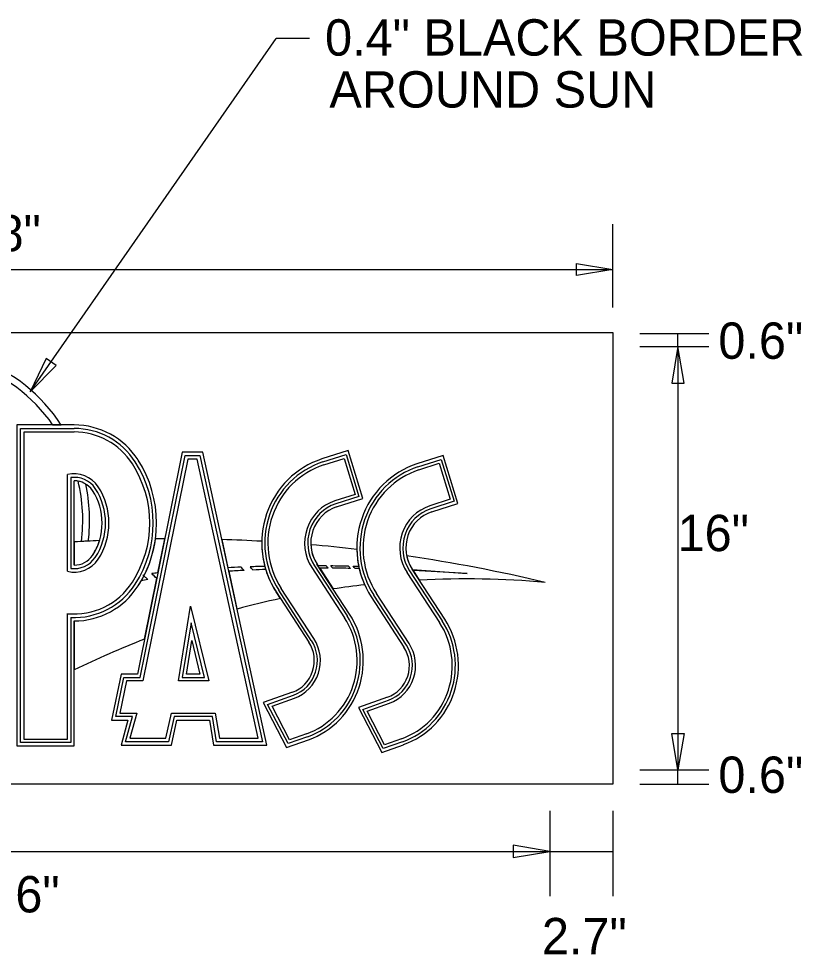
# Model space of a CAD drawing. Extents: x 10268197 to 10268738, y 2141503 to 2142677.
# Drawn here: x 10268688.05 to 10268703.13, y 2142372.22 to 2142390.23 of the extents above; entities that cross this region are included whole.
import ezdxf

# ---------------------------------------------------------------- set-up
doc = ezdxf.new("R2010")
doc.units = 0
for name, color, linetype in [('1', 7, 'Continuous'), ('Default', 7, 'Continuous'), ('GSDims', 7, 'Continuous'), ('TextMisc', 7, 'Continuous')]:
    doc.layers.add(name, color=color, linetype=linetype)

msp = doc.modelspace()

# ---------------------------------------------------------------- linework, layer by layer
at = {"layer": '1'}
for p, q in [((10268688.273, 2142383.048), (10268693.006, 2142389.854)), ((10268693.645, 2142389.854), (10268693.006, 2142389.854)), ((10268690.389, 2142377.551), (10268691.254, 2142381.823)), ((10268691.254, 2142381.823), (10268691.538, 2142381.823)), ((10268691.538, 2142381.823), (10268692.74, 2142376.315)), ((10268690.61, 2142379.551), (10268690.701, 2142379.461)), ((10268691.369, 2142378.6), (10268691.198, 2142377.551)), ((10268691.625, 2142377.551), (10268691.369, 2142378.6)), ((10268689.918, 2142376.798), (10268690.074, 2142377.551)), ((10268690.074, 2142377.551), (10268690.389, 2142377.551)), ((10268691.198, 2142377.551), (10268691.625, 2142377.551)), ((10268691.539, 2142377.618), (10268691.277, 2142377.618)), ((10268690.238, 2142376.798), (10268689.918, 2142376.798)), ((10268690.107, 2142376.315), (10268690.238, 2142376.798)), ((10268691.04, 2142376.798), (10268690.935, 2142376.315)), ((10268691.78, 2142376.798), (10268691.04, 2142376.798)), ((10268691.859, 2142376.315), (10268691.78, 2142376.798)), ((10268689.836, 2142376.731), (10268690.15, 2142376.731)), ((10268690.935, 2142376.315), (10268690.107, 2142376.315)), ((10268692.74, 2142376.315), (10268691.859, 2142376.315)), ((10268699.488, 2142375.495), (10268675.901, 2142375.495))]:
    msp.add_line(p, q, dxfattribs=at)
for points in [[(10268690.15, 2142376.731), (10268690.019, 2142376.248), (10268690.989, 2142376.248), (10268691.094, 2142376.731), (10268691.723, 2142376.731), (10268691.802, 2142376.248), (10268692.824, 2142376.248), (10268691.592, 2142381.89), (10268691.199, 2142381.89), (10268690.334, 2142377.618), (10268690.019, 2142377.618), (10268689.836, 2142376.731)], [(10268690.442, 2142379.529), (10268690.538, 2142379.435), (10268690.409, 2142379.413)], [(10268691.277, 2142377.618), (10268691.382, 2142378.263), (10268691.539, 2142377.618)]]:
    msp.add_lwpolyline(points, dxfattribs=at)
at = {"layer": 'Default'}
for p, q in [((10268688.709, 2142382.412), (10268688.869, 2142382.412)), ((10268688.083, 2142376.299), (10268688.083, 2142382.345)), ((10268688.083, 2142382.345), (10268689.118, 2142382.345)), ((10268688.148, 2142382.277), (10268688.148, 2142376.366)), ((10268689.118, 2142382.277), (10268688.148, 2142382.277)), ((10268688.148, 2142382.277), (10268688.148, 2142376.366)), ((10268689.118, 2142382.277), (10268688.148, 2142382.277)), ((10268693.902, 2142381.7), (10268694.351, 2142381.845)), ((10268694.351, 2142381.845), (10268694.599, 2142381.038)), ((10268691.305, 2142381.756), (10268690.44, 2142377.484)), ((10268691.305, 2142381.756), (10268690.44, 2142377.484)), ((10268691.487, 2142381.756), (10268691.305, 2142381.756)), ((10268691.487, 2142381.756), (10268691.305, 2142381.756)), ((10268692.66, 2142376.382), (10268691.487, 2142381.756)), ((10268692.66, 2142376.382), (10268691.487, 2142381.756)), ((10268693.92, 2142381.642), (10268694.312, 2142381.769)), ((10268693.92, 2142381.642), (10268694.312, 2142381.769)), ((10268694.312, 2142381.769), (10268694.525, 2142381.077)), ((10268694.312, 2142381.769), (10268694.525, 2142381.077)), ((10268695.733, 2142381.605), (10268696.181, 2142381.75)), ((10268695.751, 2142381.547), (10268696.143, 2142381.674)), ((10268695.751, 2142381.547), (10268696.143, 2142381.674)), ((10268696.143, 2142381.674), (10268696.356, 2142380.982)), ((10268696.143, 2142381.674), (10268696.356, 2142380.982)), ((10268696.181, 2142381.75), (10268696.43, 2142380.943)), ((10268688.987, 2142379.595), (10268688.987, 2142381.456)), ((10268688.987, 2142379.595), (10268688.987, 2142381.456)), ((10268689.053, 2142381.399), (10268689.053, 2142379.651)), ((10268689.118, 2142379.714), (10268689.118, 2142381.337)), ((10268694.525, 2142381.077), (10268694.133, 2142380.951)), ((10268694.525, 2142381.077), (10268694.133, 2142380.951)), ((10268694.599, 2142381.038), (10268694.151, 2142380.893)), ((10268696.356, 2142380.982), (10268695.964, 2142380.855)), ((10268696.356, 2142380.982), (10268695.964, 2142380.855)), ((10268696.43, 2142380.943), (10268695.982, 2142380.797)), ((10268690.728, 2142379.565), (10268690.861, 2142380.22)), ((10268689.118, 2142380.161), (10268689.118, 2142379.714)), ((10268691.959, 2142380.207), (10268692.078, 2142379.664)), ((10268689.469, 2142379.899), (10268689.469, 2142379.899)), ((10268693.742, 2142379.701), (10268694.369, 2142378.736)), ((10268694.418, 2142378.769), (10268693.791, 2142379.734)), ((10268693.791, 2142379.734), (10268693.812, 2142379.701)), ((10268692.093, 2142379.596), (10268692.251, 2142378.87)), ((10268693.693, 2142379.667), (10268694.32, 2142378.702)), ((10268693.693, 2142379.667), (10268694.32, 2142378.702)), ((10268693.843, 2142379.653), (10268694.102, 2142379.256)), ((10268695.523, 2142379.572), (10268696.151, 2142378.607)), ((10268695.523, 2142379.572), (10268696.151, 2142378.607)), ((10268695.572, 2142379.605), (10268696.2, 2142378.64)), ((10268696.249, 2142378.674), (10268695.621, 2142379.639)), ((10268695.621, 2142379.639), (10268695.627, 2142379.63)), ((10268695.627, 2142379.63), (10268696.682, 2142379.553)), ((10268696.682, 2142379.553), (10268695.641, 2142379.608)), ((10268695.641, 2142379.608), (10268695.76, 2142379.425)), ((10268690.348, 2142379.313), (10268690.348, 2142379.313)), ((10268690.469, 2142378.288), (10268690.707, 2142379.46)), ((10268693.006, 2142379.198), (10268693.633, 2142378.232)), ((10268693.088, 2142379.071), (10268693.006, 2142379.198)), ((10268693.682, 2142378.266), (10268693.055, 2142379.231)), ((10268693.731, 2142378.3), (10268693.104, 2142379.265)), ((10268693.731, 2142378.3), (10268693.104, 2142379.265)), ((10268695.513, 2142378.171), (10268694.885, 2142379.136)), ((10268695.562, 2142378.204), (10268694.934, 2142379.169)), ((10268695.562, 2142378.204), (10268694.934, 2142379.169)), ((10268694.836, 2142379.102), (10268695.464, 2142378.137)), ((10268688.987, 2142376.366), (10268688.987, 2142378.78)), ((10268688.987, 2142376.366), (10268688.987, 2142378.78)), ((10268691.123, 2142377.484), (10268691.356, 2142378.922)), ((10268691.123, 2142377.484), (10268691.356, 2142378.922)), ((10268691.356, 2142378.922), (10268691.707, 2142377.484)), ((10268691.356, 2142378.922), (10268691.707, 2142377.484)), ((10268689.053, 2142378.708), (10268689.053, 2142376.299)), ((10268689.118, 2142378.639), (10268689.118, 2142377.696)), ((10268690.125, 2142377.484), (10268689.997, 2142376.866)), ((10268690.125, 2142377.484), (10268689.997, 2142376.866)), ((10268690.44, 2142377.484), (10268690.125, 2142377.484)), ((10268690.44, 2142377.484), (10268690.125, 2142377.484)), ((10268691.707, 2142377.484), (10268691.123, 2142377.484)), ((10268691.707, 2142377.484), (10268691.123, 2142377.484)), ((10268692.841, 2142377.033), (10268693.336, 2142377.209)), ((10268692.925, 2142376.999), (10268693.355, 2142377.152)), ((10268692.925, 2142376.999), (10268693.355, 2142377.152)), ((10268693.234, 2142376.277), (10268692.841, 2142377.033)), ((10268693.262, 2142376.351), (10268692.925, 2142376.999)), ((10268693.262, 2142376.351), (10268692.925, 2142376.999)), ((10268694.672, 2142376.937), (10268695.167, 2142377.114)), ((10268694.756, 2142376.903), (10268695.186, 2142377.057)), ((10268694.756, 2142376.903), (10268695.186, 2142377.057)), ((10268689.997, 2142376.866), (10268690.323, 2142376.866)), ((10268689.997, 2142376.866), (10268690.323, 2142376.866)), ((10268690.323, 2142376.866), (10268690.192, 2142376.382)), ((10268690.323, 2142376.866), (10268690.192, 2142376.382)), ((10268690.884, 2142376.382), (10268690.989, 2142376.866)), ((10268690.884, 2142376.382), (10268690.989, 2142376.866)), ((10268690.989, 2142376.866), (10268691.834, 2142376.866)), ((10268690.989, 2142376.866), (10268691.834, 2142376.866)), ((10268691.834, 2142376.866), (10268691.913, 2142376.382)), ((10268691.834, 2142376.866), (10268691.913, 2142376.382)), ((10268695.065, 2142376.181), (10268694.672, 2142376.937)), ((10268695.093, 2142376.255), (10268694.756, 2142376.903)), ((10268695.093, 2142376.255), (10268694.756, 2142376.903)), ((10268693.588, 2142376.467), (10268693.262, 2142376.351)), ((10268693.588, 2142376.467), (10268693.262, 2142376.351)), ((10268689.053, 2142376.299), (10268688.083, 2142376.299)), ((10268688.148, 2142376.366), (10268688.987, 2142376.366)), ((10268688.148, 2142376.366), (10268688.987, 2142376.366)), ((10268690.192, 2142376.382), (10268690.884, 2142376.382)), ((10268690.192, 2142376.382), (10268690.884, 2142376.382)), ((10268691.913, 2142376.382), (10268692.66, 2142376.382)), ((10268691.913, 2142376.382), (10268692.66, 2142376.382)), ((10268693.607, 2142376.41), (10268693.234, 2142376.277)), ((10268695.438, 2142376.314), (10268695.065, 2142376.181)), ((10268695.419, 2142376.371), (10268695.093, 2142376.255)), ((10268695.419, 2142376.371), (10268695.093, 2142376.255)), ((10268699.488, 2142375.495), (10268675.901, 2142375.495))]:
    msp.add_line(p, q, dxfattribs=at)
for points in [[(10268675.901, 2142375.495), (10268675.901, 2142384.193), (10268699.488, 2142384.193), (10268699.488, 2142375.495)], [(10268689.118, 2142382.412), (10268688.017, 2142382.412), (10268688.017, 2142376.232), (10268689.118, 2142376.232), (10268689.118, 2142378.639)], [(10268694.169, 2142380.835), (10268694.673, 2142380.999), (10268694.389, 2142381.921), (10268693.885, 2142381.758)], [(10268690.293, 2142381.701), (10268690.293, 2142381.701)], [(10268695.999, 2142380.74), (10268696.504, 2142380.903), (10268696.22, 2142381.826), (10268695.715, 2142381.662)], [(10268689.524, 2142381.189), (10268689.523, 2142381.19)], [(10268689.469, 2142379.899), (10268689.469, 2142379.899)], [(10268689.523, 2142379.861), (10268689.524, 2142379.862)], [(10268690.461, 2142379.51), (10268690.538, 2142379.435), (10268690.409, 2142379.413)], [(10268690.293, 2142379.35), (10268690.293, 2142379.35)], [(10268690.348, 2142379.313), (10268690.348, 2142379.313)], [(10268690.707, 2142379.46), (10268690.701, 2142379.461)], [(10268693.317, 2142377.266), (10268692.756, 2142377.067), (10268693.206, 2142376.203), (10268693.627, 2142376.353)], [(10268695.147, 2142377.171), (10268694.587, 2142376.971), (10268695.037, 2142376.107), (10268695.457, 2142376.257)]]:
    msp.add_lwpolyline(points, dxfattribs=at)
for centre, major_axis, ratio, start_param, end_param in [((10268686.203, 2142380.578), (0, 3.29), 0.97582, 5.303349, 7.802858), ((10268686.203, 2142380.578), (0, 3.29), 0.97582, 5.303349, 7.802858), ((10268686.203, 2142380.578), (0, 3.156), 0.97582, 5.332201, 7.884008), ((10268686.203, 2142380.578), (0, 3.156), 0.97582, 5.332201, 7.884008), ((10268689.121, 2142380.903), (0, 1.509), 0.97582, 5.298823, 6.285263), ((10268689.121, 2142380.903), (0, 1.442), 0.97582, 5.29886, 6.285263), ((10268689.118, 2142380.928), (0, 1.35), 0.990269, 5.289759, 6.283185), ((10268689.118, 2142380.928), (0, 1.35), 0.990269, 5.289759, 6.283185), ((10268688.507, 2142380.525), (0, 2.087), 0.989796, 4.135019, 5.289759), ((10268688.507, 2142380.525), (0, 2.087), 0.989796, 4.135019, 5.289759), ((10268689.121, 2142380.903), (0, 1.442), 0.97582, 5.298823, 5.29886), ((10268688.56, 2142380.525), (0, 2.13), 0.97582, 4.127723, 5.297054), ((10268688.56, 2142380.525), (0, 2.13), 0.97582, 5.297054, 5.297084), ((10268688.56, 2142380.525), (0, 2.197), 0.97582, 4.127694, 5.297084), ((10268694.384, 2142380.139), (0, 1.698), 0.97582, 0.306207, 2.15869), ((10268694.384, 2142380.139), (0, 1.637), 0.97582, 0.306207, 2.15869), ((10268696.215, 2142380.044), (0, 1.698), 0.97582, 0.306207, 2.15869), ((10268689.118, 2142380.928), (0.55, 0), 0.987937, 0.57737, 1.811353), ((10268689.118, 2142380.928), (0.55, 0), 0.987937, 0.57737, 1.811353), ((10268694.383, 2142380.139), (0, 1.576), 0.975477, 0.305879, 2.158799), ((10268694.383, 2142380.139), (0, 1.576), 0.975477, 0.305879, 2.158799), ((10268696.215, 2142380.044), (0, 1.637), 0.97582, 0.306207, 2.15869), ((10268696.214, 2142380.044), (0, 1.576), 0.975477, 0.305879, 2.158799), ((10268696.214, 2142380.044), (0, 1.576), 0.975477, 0.305879, 2.158799), ((10268689.122, 2142380.903), (0, 0.501), 0.97582, 5.321397, 6.424928), ((10268689.122, 2142380.903), (0, 0.434), 0.97582, 5.321397, 6.29161), ((10268686.203, 2142380.578), (0, 3.156), 0.97582, 4.58247, 4.952925), ((10268689.118, 2142380.928), (0.419, 0), 0.976302, 1.01124, 1.389925), ((10268686.203, 2142380.578), (0, 3.156), 0.97582, 4.58247, 4.952925), ((10268686.203, 2142380.578), (0, 3.29), 0.97582, 4.590045, 4.925551), ((10268686.203, 2142380.578), (0, 3.29), 0.97582, 4.590045, 4.925551), ((10268688.561, 2142380.525), (0, 1.122), 0.97582, 4.120664, 5.304114), ((10268688.561, 2142380.525), (0, 1.189), 0.97582, 4.120664, 5.304114), ((10268688.507, 2142380.525), (0, 1.281), 0.998806, 4.135019, 5.289759), ((10268688.507, 2142380.525), (0, 1.281), 0.998806, 4.135019, 5.289759), ((10268694.383, 2142380.139), (0, 0.851), 0.975477, 0.305879, 2.158799), ((10268694.383, 2142380.139), (0, 0.851), 0.975477, 0.305879, 2.158799), ((10268694.384, 2142380.139), (0, 0.791), 0.97582, 0.306207, 2.15869), ((10268694.384, 2142380.139), (0, 0.73), 0.97582, 0.306207, 2.15869), ((10268696.214, 2142380.044), (0, 0.851), 0.975477, 0.305879, 2.158799), ((10268696.214, 2142380.044), (0, 0.851), 0.975477, 0.305879, 2.158799), ((10268696.214, 2142380.044), (0, 0.791), 0.97582, 0.306207, 2.15869), ((10268696.214, 2142380.044), (0, 0.73), 0.97582, 0.306207, 2.15869), ((10268688.56, 2142380.525), (0, 2.197), 0.97582, 4.232077, 4.572378), ((10268691.033, 2142348.643), (0, -31.577), 0.98893, 3.147118, 3.152801), ((10268691.033, 2142348.643), (0, -31.577), 0.98893, 3.147118, 3.152801), ((10268691.033, 2142348.643), (0, -31.577), 0.98893, 3.187344, 3.202947), ((10268691.033, 2142348.643), (0, -31.577), 0.98893, 3.187344, 3.202947), ((10268691.033, 2142348.643), (0, -31.577), 0.98893, 3.194251, 3.198517), ((10268688.561, 2142380.525), (0, 1.122), 0.97582, 4.120664, 4.406744), ((10268691.033, 2142348.643), (0, -31.577), 0.98893, 3.087298, 3.111926), ((10268691.033, 2142348.643), (0, -31.577), 0.98893, 3.087298, 3.111926), ((10268694.384, 2142380.139), (0, 1.698), 0.97582, 1.5501, 1.838244), ((10268691.033, 2142348.643), (0, -31.577), 0.98893, 3.028464, 3.056997), ((10268691.033, 2142348.643), (0, -31.577), 0.98893, 3.028464, 3.056997), ((10268694.384, 2142380.139), (0, 0.73), 0.97582, 1.61365, 2.15869), ((10268689.121, 2142380.149), (0, 0.502), 0.97582, 3.001239, 4.102113), ((10268689.121, 2142380.149), (0, 0.435), 0.97582, 3.134436, 4.102113), ((10268689.121, 2142380.149), (0, 0.435), 0.97582, 3.134436, 4.102113), ((10268696.215, 2142380.044), (0, 1.698), 0.97582, 1.58538, 1.781939), ((10268691.033, 2142348.643), (0, -31.577), 0.98893, 2.910551, 2.997508), ((10268691.033, 2142348.643), (0, -31.577), 0.98893, 2.910551, 2.997508), ((10268696.214, 2142380.044), (0, 0.73), 0.97582, 1.777902, 2.15869), ((10268689.118, 2142380.123), (0.55, 0), 0.987937, 4.471833, 5.705815), ((10268689.118, 2142380.123), (0.55, 0), 0.987937, 4.471833, 5.705815), ((10268693.644, 2142346.461), (0, -33.24), 0.988257, 3.181604, 3.189295), ((10268677.555, 2142365.833), (0, 20.419), 0.984327, 5.453123, 5.457325), ((10268693.644, 2142346.461), (0, -33.24), 0.988257, 3.167715, 3.176345), ((10268677.555, 2142365.833), (0, 20.553), 0.98427, 5.447702, 5.451744), ((10268693.644, 2142346.461), (0, -33.24), 0.988257, 3.131695, 3.136489), ((10268677.555, 2142365.833), (0, 21.695), 0.983807, 5.403078, 5.405838), ((10268693.644, 2142346.461), (0, -33.24), 0.988257, 3.118574, 3.129071), ((10268677.555, 2142365.833), (0, 21.763), 0.983781, 5.400528, 5.403217), ((10268677.555, 2142365.833), (0, 22.031), 0.98368, 5.390405, 5.392813), ((10268677.555, 2142365.833), (0, 22.098), 0.983655, 5.387892, 5.390232), ((10268693.644, 2142346.461), (0, -33.24), 0.988257, 3.112651, 3.11595), ((10268692.076, 2142367.544), (0, -12.098), 0.987081, 3.2547, 3.264672), ((10268677.555, 2142365.833), (0, 19.076), 0.984951, 5.508238, 5.514999), ((10268694.04, 2142346.414), (0, -33.24), 0.988257, 3.191919, 3.200901), ((10268694.04, 2142346.414), (0, -33.24), 0.988257, 3.179241, 3.186723), ((10268694.384, 2142380.139), (0, 1.698), 0.97582, 1.875041, 2.15869), ((10268694.04, 2142346.414), (0, -33.24), 0.988257, 3.142595, 3.147585), ((10268694.04, 2142346.414), (0, -33.24), 0.988257, 3.129621, 3.14), ((10268694.04, 2142346.414), (0, -33.24), 0.988257, 3.124437, 3.127026), ((10268696.215, 2142380.044), (0, 1.698), 0.97582, 1.805305, 2.000126), ((10268689.118, 2142380.123), (0, 1.35), 0.990269, 3.043371, 4.135019), ((10268689.118, 2142380.123), (0, 1.35), 0.990269, 3.043371, 4.135019), ((10268689.121, 2142380.148), (0, 1.442), 0.97582, 3.092812, 4.125918), ((10268689.121, 2142380.148), (0, 1.509), 0.97582, 3.139515, 4.125955), ((10268689.121, 2142380.148), (0, 1.509), 0.97582, 3.139515, 4.125955), ((10268689.121, 2142380.148), (0, 1.442), 0.97582, 4.125918, 4.125955), ((10268688.56, 2142380.525), (0, 2.13), 0.97582, 4.127694, 4.127723), ((10268688.56, 2142380.525), (0, 2.197), 0.97582, 4.127694, 4.181576), ((10268696.665, 2142361.504), (0, 17.945), 0.975477, 0.111981, 0.146944), ((10268696.665, 2142361.504), (0, 17.945), 0.975477, 0.111981, 0.146944), ((10268696.665, 2142361.504), (0, 17.945), 0.975477, 6.196281, 6.334881), ((10268696.665, 2142361.504), (0, 17.945), 0.975477, 6.196281, 6.334881), ((10268696.665, 2142361.504), (0, 17.945), 0.975477, 0.20577, 0.254866), ((10268696.665, 2142361.504), (0, 17.945), 0.975477, 0.20577, 0.254866), ((10268693.11, 2142377.875), (0, -1.491), 0.975477, 0.334737, 2.158799), ((10268693.11, 2142377.875), (0, -1.491), 0.975477, 0.334737, 2.158799), ((10268693.109, 2142377.875), (0, 1.552), 0.97582, 3.476656, 5.300276), ((10268693.109, 2142377.875), (0, 1.612), 0.97582, 3.476656, 5.300276), ((10268694.941, 2142377.78), (0, -1.491), 0.975477, 0.334737, 2.158799), ((10268694.941, 2142377.78), (0, -1.491), 0.975477, 0.334737, 2.158799), ((10268694.94, 2142377.78), (0, 1.552), 0.97582, 3.476656, 5.300276), ((10268694.94, 2142377.78), (0, 1.612), 0.97582, 3.476656, 5.300276), ((10268696.665, 2142361.504), (0, 17.945), 0.975477, 0.36175, 0.445699), ((10268696.665, 2142361.504), (0, 17.945), 0.975477, 0.36175, 0.445699), ((10268693.11, 2142377.875), (0, 0.645), 0.97582, 3.476661, 5.300276), ((10268693.11, 2142377.875), (0, 0.705), 0.97582, 3.476661, 5.300276), ((10268693.11, 2142377.875), (0, -0.765), 0.975477, 0.334742, 2.158799), ((10268693.11, 2142377.875), (0, -0.765), 0.975477, 0.334742, 2.158799), ((10268694.94, 2142377.78), (0, 0.645), 0.97582, 3.476661, 5.300276), ((10268694.94, 2142377.78), (0, 0.705), 0.97582, 3.476661, 5.300276), ((10268694.941, 2142377.78), (0, -0.765), 0.975477, 0.334742, 2.158799), ((10268694.941, 2142377.78), (0, -0.765), 0.975477, 0.334742, 2.158799)]:
    msp.add_ellipse(centre, major_axis=major_axis, ratio=ratio, start_param=start_param, end_param=end_param, dxfattribs=at)
at = {"layer": 'GSDims'}
for p, q in [((10268675.901, 2142385.405), (10268699.488, 2142385.405)), ((10268700.006, 2142384.176), (10268701.33, 2142384.176)), ((10268700.737, 2142383.921), (10268700.737, 2142384.176)), ((10268700.006, 2142383.921), (10268701.33, 2142383.921)), ((10268700.737, 2142383.921), (10268700.737, 2142375.77)), ((10268700.006, 2142375.77), (10268701.33, 2142375.77)), ((10268700.737, 2142375.495), (10268700.737, 2142375.77)), ((10268700.006, 2142375.495), (10268701.33, 2142375.495)), ((10268698.271, 2142374.982), (10268698.271, 2142373.342)), ((10268699.488, 2142374.982), (10268699.488, 2142373.342)), ((10268677.148, 2142374.203), (10268698.271, 2142374.203)), ((10268698.271, 2142374.203), (10268699.488, 2142374.203))]:
    msp.add_line(p, q, dxfattribs=at)
for points in [[(10268699.488, 2142385.405), (10268698.784, 2142385.288), (10268698.784, 2142385.522)], [(10268700.737, 2142383.921), (10268700.62, 2142383.217), (10268700.855, 2142383.217)], [(10268688.273, 2142383.048), (10268688.772, 2142383.559), (10268688.579, 2142383.693)], [(10268700.737, 2142375.77), (10268700.62, 2142376.474), (10268700.855, 2142376.474)], [(10268698.271, 2142374.203), (10268697.567, 2142374.32), (10268697.567, 2142374.085)]]:
    msp.add_lwpolyline(points, close=True, dxfattribs=at)
at = {"layer": 'TextMisc'}
msp.add_line((10268699.488, 2142384.671), (10268699.488, 2142386.279), dxfattribs=at)

# ---------------------------------------------------------------- texts
at = {"layer": '1'}
for s, p in [('0.4" BLACK BORDER', (10268693.946, 2142389.523)), ('AROUND SUN', (10268694.03, 2142388.523)), ('48"', (10268687.103, 2142385.755)), ('0.6"', (10268701.516, 2142383.686)), ('16"', (10268700.731, 2142379.983)), ('0.6"', (10268701.516, 2142375.329)), ('42.6"', (10268686.684, 2142373.028)), ('2.7"', (10268698.12, 2142372.222))]:
    msp.add_text(s, height=0.7, dxfattribs=at).set_placement(p)

doc.saveas('drawing.dxf')
